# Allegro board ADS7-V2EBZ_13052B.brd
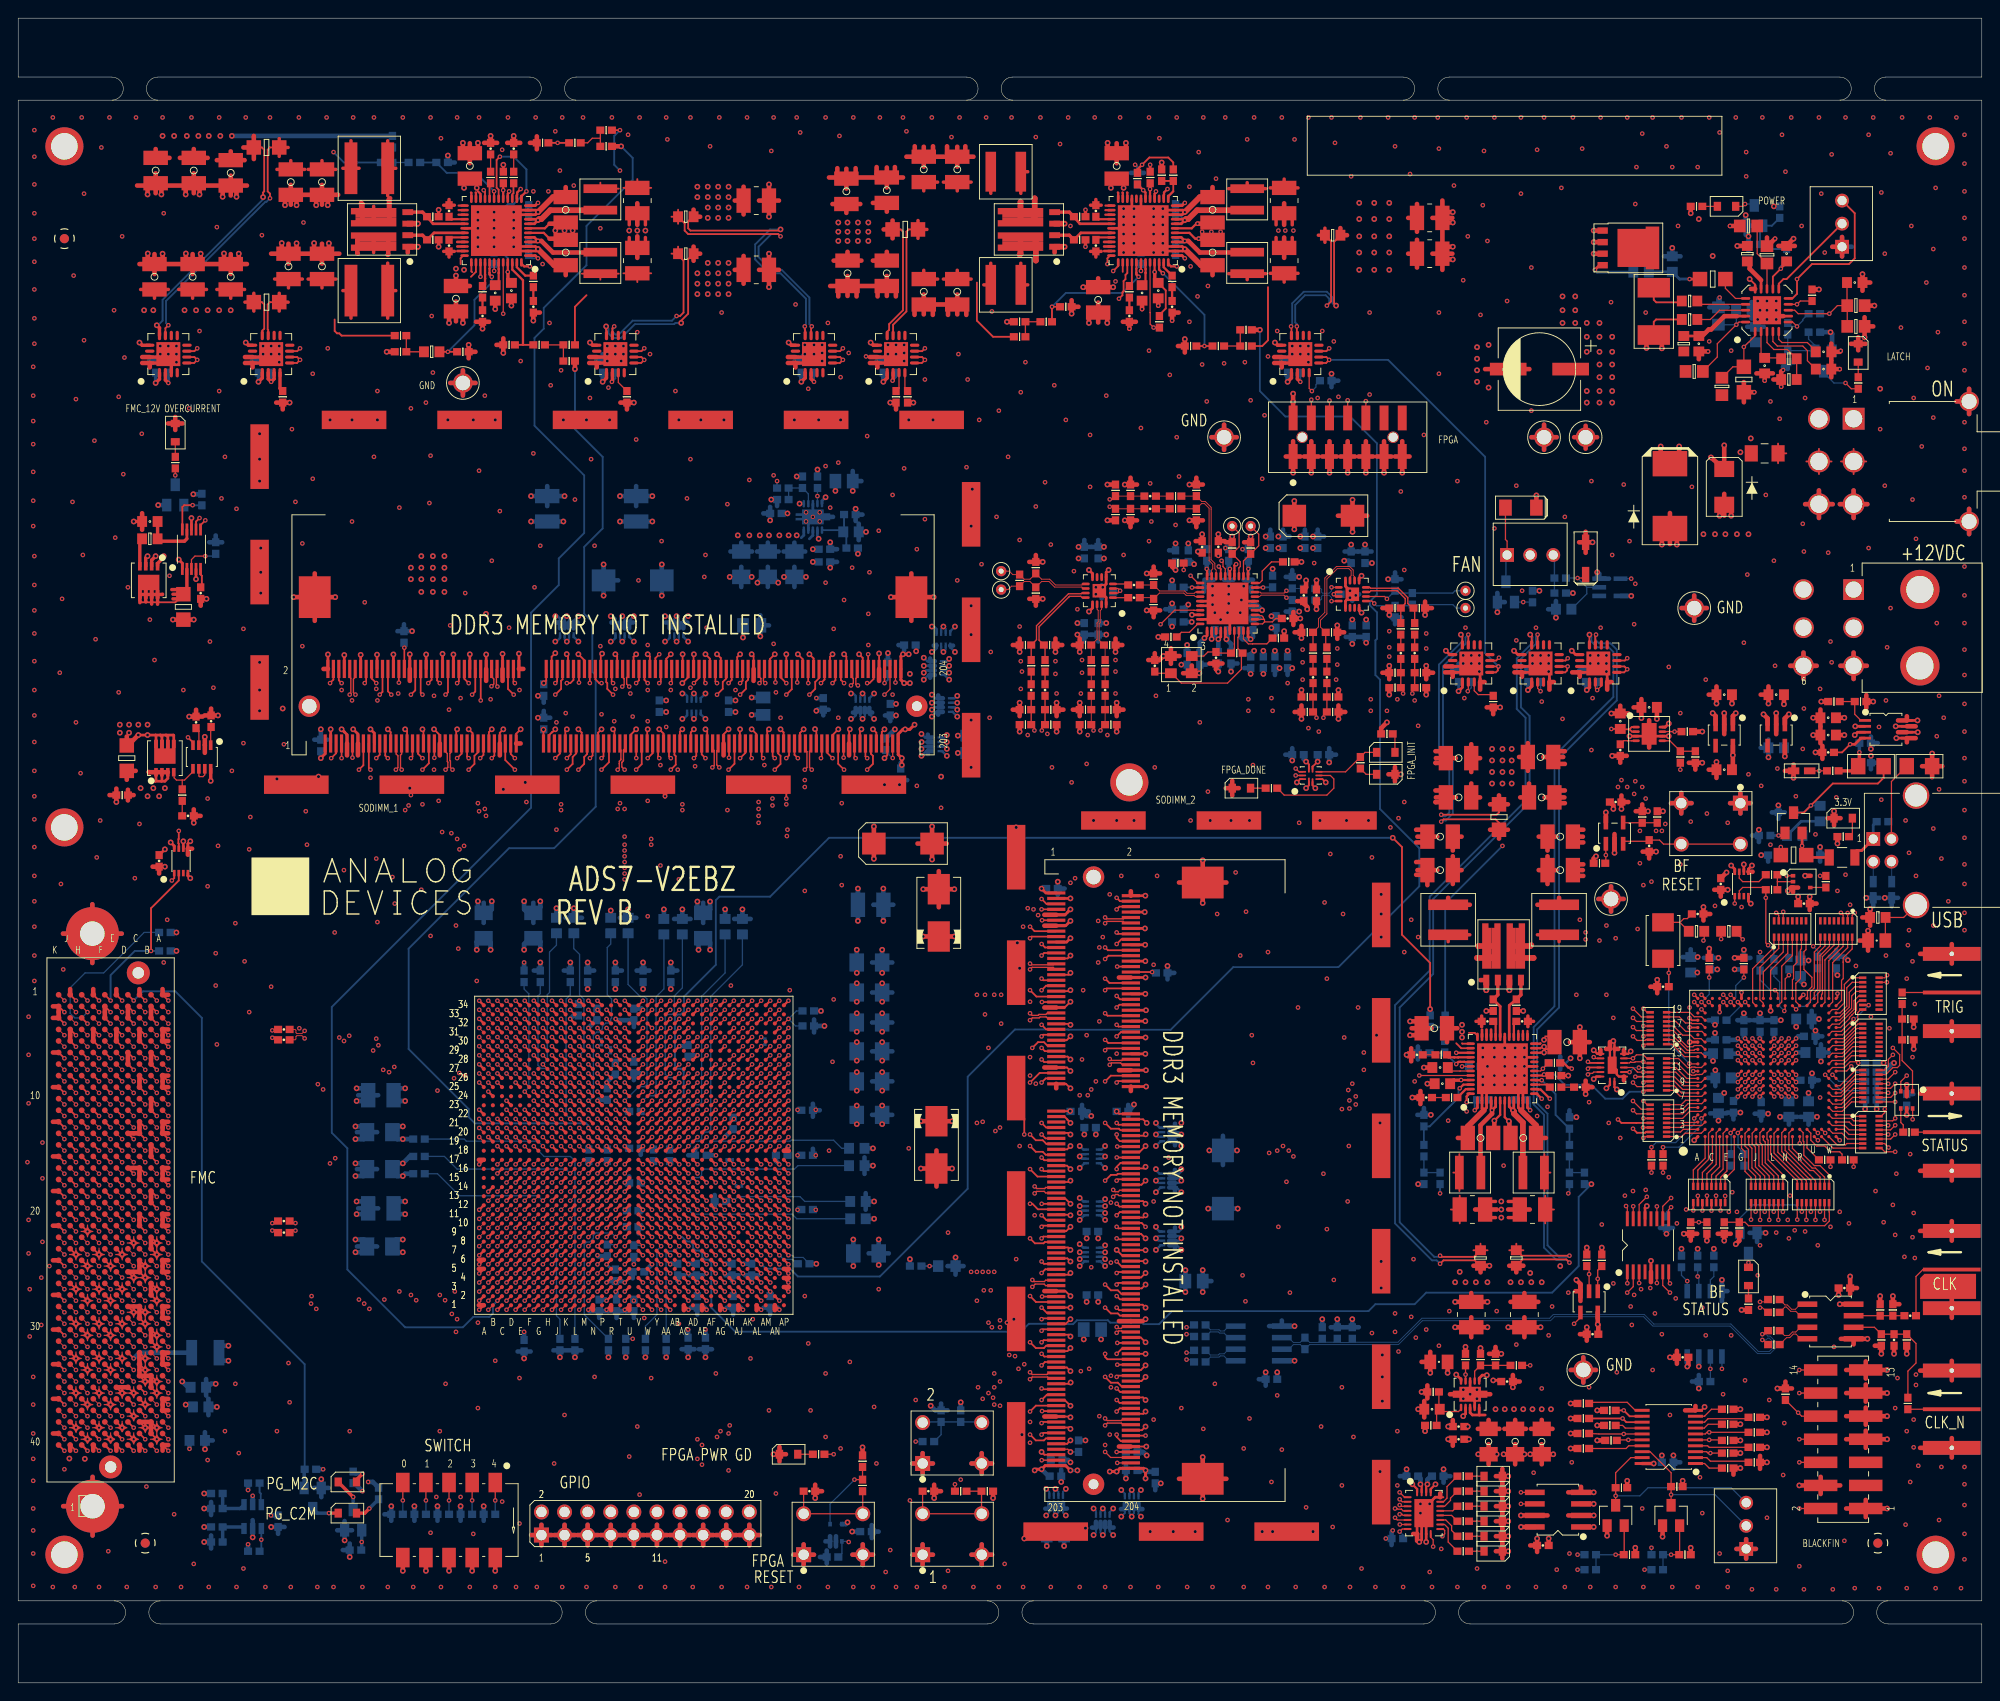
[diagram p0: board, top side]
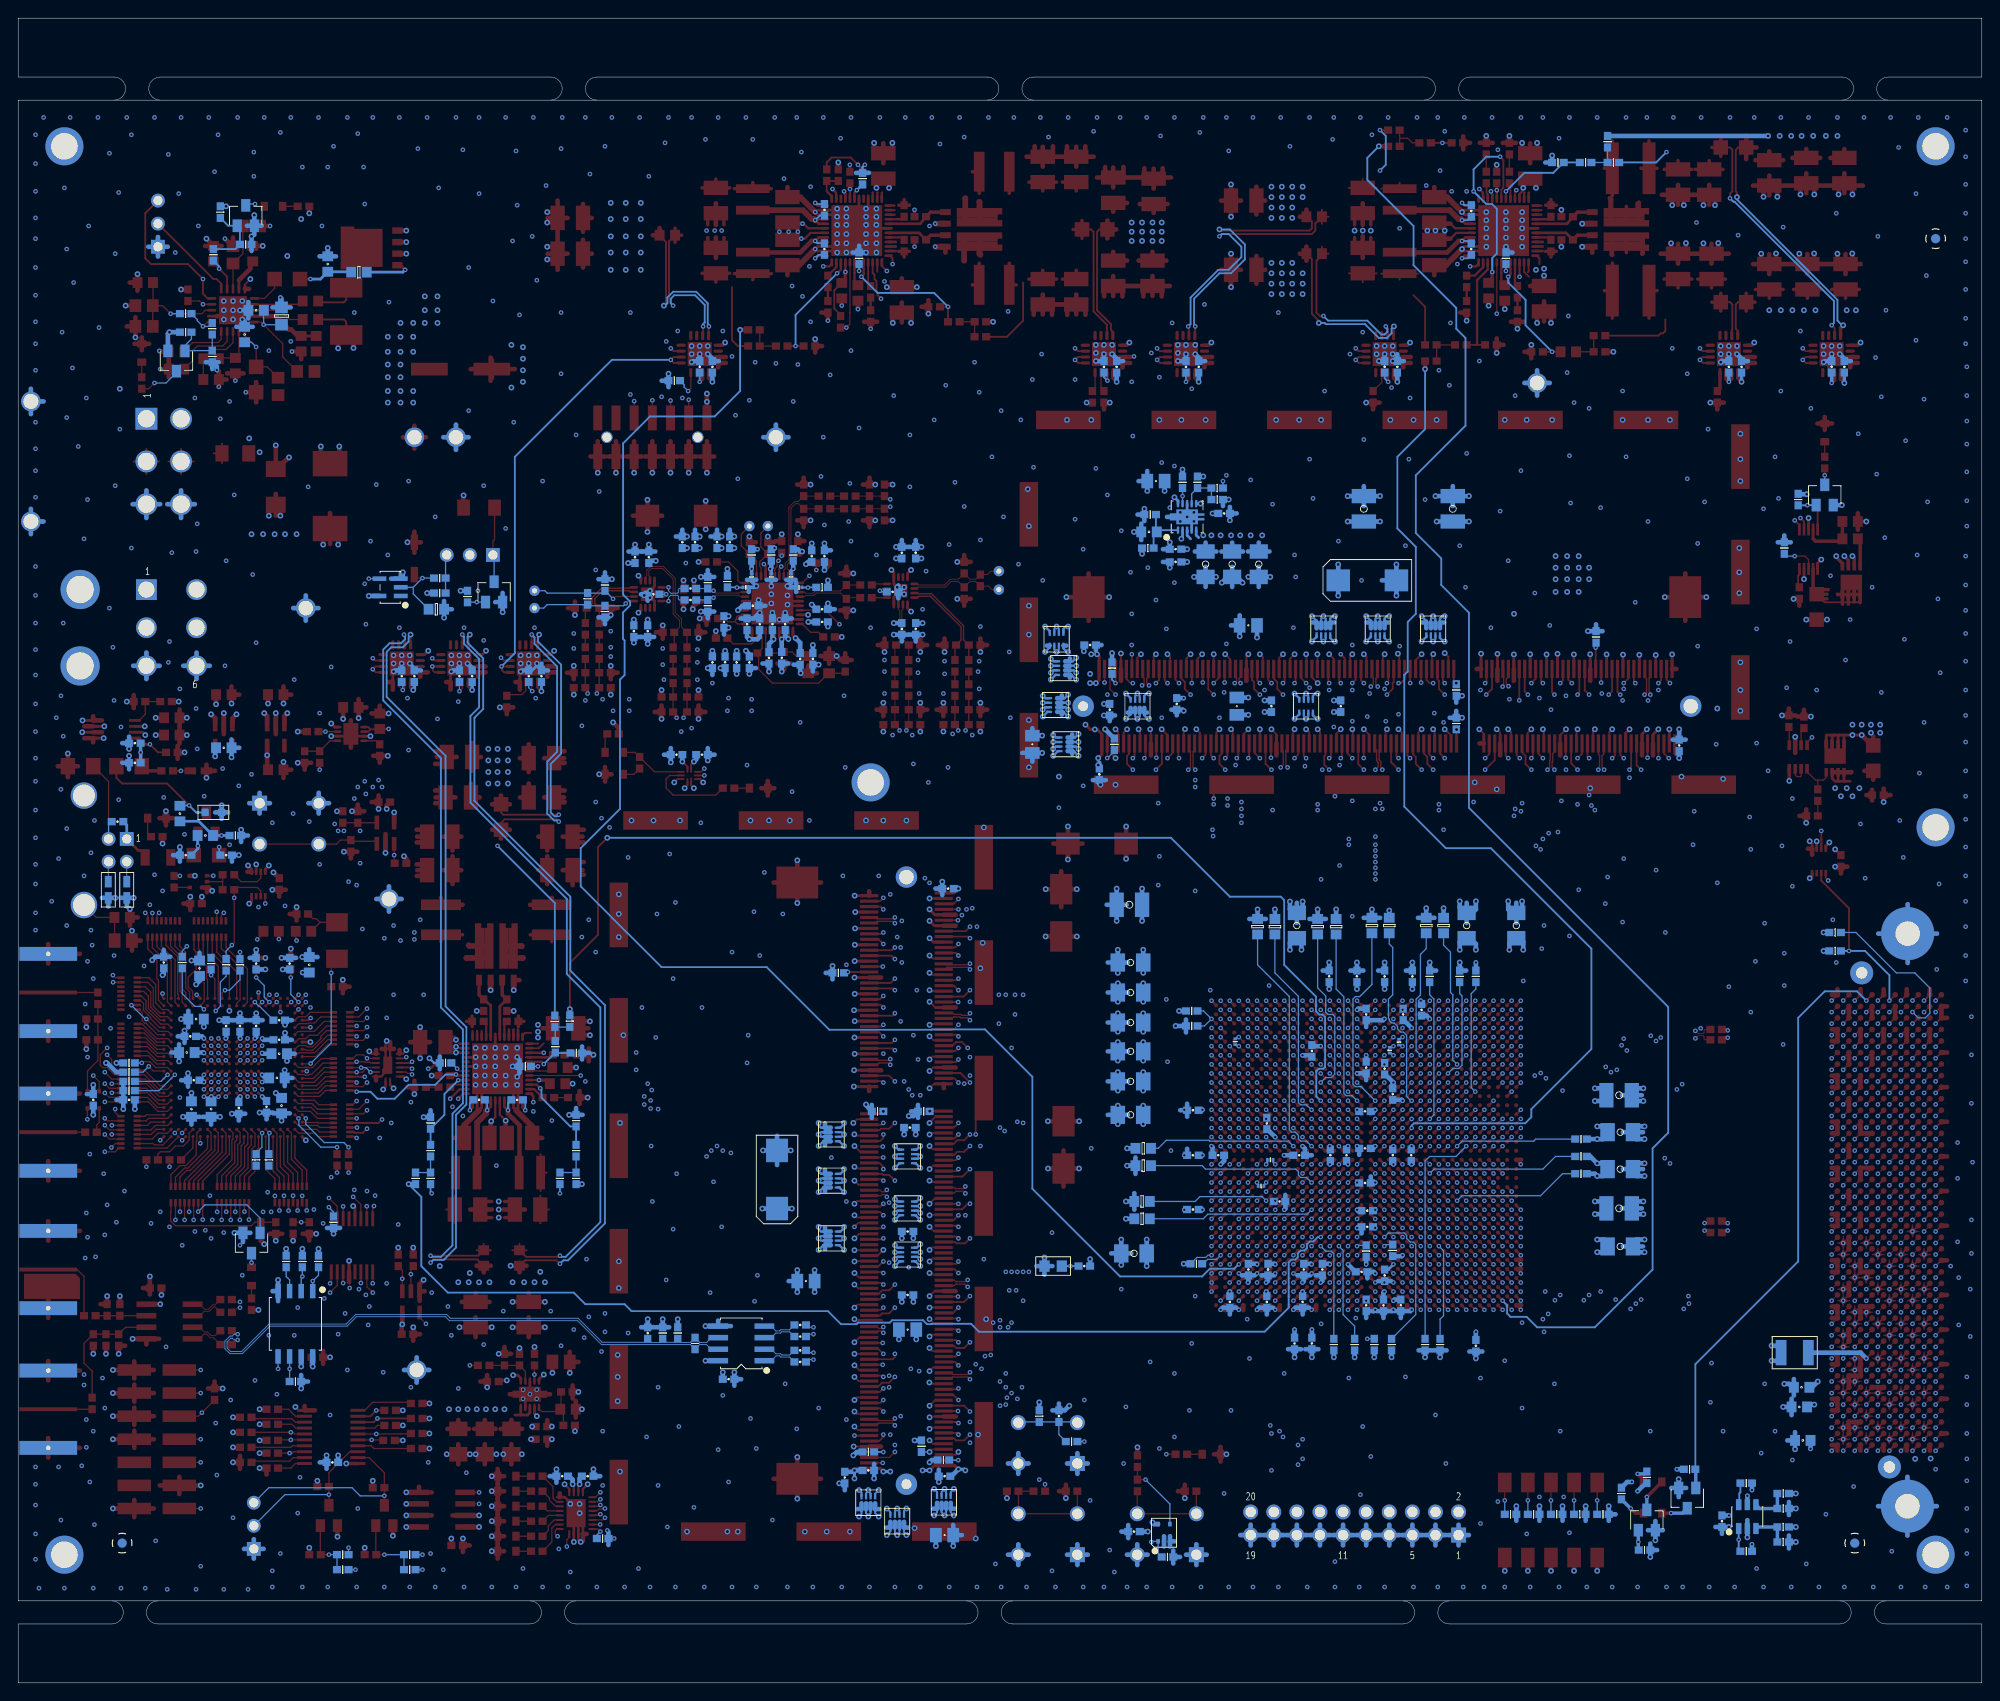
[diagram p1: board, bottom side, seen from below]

Outline 215.9 x 183.13 mm; copper layers: TOP, L2_GROUND, L3_SIGNAL, L4_GROUND, L5_SIGNAL, L6_GROUND, L7_SIGNAL, L8_GROUND, L9_SIGNAL, L10_GROUND, L11_POWER, L12_POWER, L13_POWER, L14_POWER, L15_GROUND, L16_SIGNAL, L17_GROUND, L18_SIGNAL, L19_GROUND, L20_SIGNAL, L21_GROUND, L22_SIGNAL, L23_GROUND, BOTTOM. Coordinates in mm from the lower left corner of the outline.
Outline path: 10.54,6.48 0,6.48 0,0 215.9,0 215.9,6.48 205.61,6.48 arc(204.34,7.75) 205.61,9.02 ; 10.29,174.12 arc(11.56,175.39) 10.29,176.66 0,176.66 0,183.13 215.9,183.13 215.9,176.66 205.36,176.66 ; 10.54,9.01 arc(11.81,7.75) 10.54,6.48 ; 15.37,174.12 arc(14.1,175.39) 15.37,176.66 56.26,176.66 ; 15.62,6.48 arc(14.36,7.75) 15.62,9.02 ; 15.62,6.48 58.55,6.48 ; 56.26,176.66 arc(57.53,175.38) 56.26,174.12 ; 58.54,9.01 arc(59.81,7.75) 58.54,6.48 ; 61.34,174.12 arc(60.08,175.39) 61.35,176.66 ; 63.62,6.48 arc(62.36,7.75) 63.63,9.02 ; 63.63,6.48 106.55,6.48 ; 104.27,176.66 61.34,176.66 ; 104.27,176.66 arc(105.53,175.38) 104.26,174.12 ; 106.55,9.01 arc(107.82,7.75) 106.55,6.48 ; 109.35,174.12 arc(108.08,175.39) 109.35,176.66 ; 111.63,6.48 arc(110.37,7.75) 111.64,9.02 ; 111.63,6.48 154.56,6.48 ; 152.27,176.66 109.35,176.66 ; 152.28,176.66 arc(153.54,175.38) 152.27,174.12 ; 154.56,9.01 arc(155.82,7.75) 154.55,6.48 ; 157.36,174.12 arc(156.09,175.39) 157.36,176.66 ; 159.64,6.48 arc(158.37,7.75) 159.64,9.02 ; 159.64,6.48 200.53,6.48 arc(201.8,7.75) 200.53,9.02 ; 200.28,176.66 157.35,176.66 ; 200.28,176.66 arc(201.54,175.38) 200.28,174.12 ; 205.36,174.12 arc(204.09,175.39) 205.36,176.66 ; 0,174.12 0,9.02 215.9,9.02 215.9,174.12 0,174.12

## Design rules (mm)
net group AD9577_OUT0_N: nets AD9577_OUT0_N UNNAMED_19_AD9577_I478_OUT0N
net group AD9577_OUT0_P: nets AD9577_OUT0_P UNNAMED_19_AD9577_I478_OUT0P
net group AD9577_OUT2_N: nets AD9577_OUT2_N UNNAMED_19_AD9577_I478_OUT2N
net group AD9577_OUT2_P: nets AD9577_OUT2_P UNNAMED_19_AD9577_I478_OUT2P
net group ADM1276_PWRGD: nets ADM1276_PWRGD UNNAMED_22_RES_I217_N2
net group ADP5054_#1_BST3: nets ADP5054_#1_BST3 UNNAMED_15_ADP5054_I113_SW31
net group ADP5054_#1_BST4: nets ADP5054_#1_BST4 UNNAMED_15_CAP_I42_N2
net group ADP5054_#2_BST3: nets ADP5054_#2_BST3 UNNAMED_20_ADP5054_I24_SW31
net group ADP5054_#2_BST4: nets ADP5054_#2_BST4 UNNAMED_20_ADP5054_I24_SW41
net group ADP5054_#3_BST3: nets ADP5054_#3_BST3 UNNAMED_21_ADP5054_I24_SW31
net group ADP5054_#3_BST4: nets ADP5054_#3_BST4 UNNAMED_21_ADP5054_I24_SW41
net group ARDY: nets ARDY UNNAMED_14_ADSPBF52XV3_I94_ARDY
net group AREB: nets AREB UNNAMED_14_ADSPBF52XV3_I94_AREN
net group BF_CLKBUF: nets BF_CLKBUF UNNAMED_10_ADSPBF52XV3_I35_USBX
net group BF_JTAG_EMU: nets BF_JTAG_EMU UNNAMED_10_ADSPBF52XV3_I35_EMU
net group BF_JTAG_TDO: nets BF_JTAG_TDO UNNAMED_10_ADSPBF52XV3_I35_TDO
net group CCLK: nets CCLK UNNAMED_1_CMOSNC7SZ125_I41_Y
net group DDR3-1_REF_EN: nets DDR3-1_REF_EN UNNAMED_24_ICTPS51200_I1_EN
net group DDR3-2_REF_EN: nets DDR3-2_REF_EN UNNAMED_24_ICTPS51200_I33_EN
net group FMC-1_CLK0_M2C: nets FMC-1_CLK0_M2C_N FMC-1_CLK0_M2C_P
net group FMC-1_CLK1_M2C: nets FMC-1_CLK1_M2C_N FMC-1_CLK1_M2C_P
net group FMC-1_CLK2_BIDIR: nets FMC-1_CLK2_BIDIR_N FMC-1_CLK2_BIDIR_P
net group FMC-1_CLK3_BIDIR: nets FMC-1_CLK3_BIDIR_N FMC-1_CLK3_BIDIR_P
net group FMC-1_DP0_C2M: nets FMC-1_DP0_C2M_N FMC-1_DP0_C2M_P
net group FMC-1_DP0_M2C: nets FMC-1_DP0_M2C_N FMC-1_DP0_M2C_P
net group FMC-1_DP1_C2M: nets FMC-1_DP1_C2M_N FMC-1_DP1_C2M_P
net group FMC-1_DP1_M2C: nets FMC-1_DP1_M2C_N FMC-1_DP1_M2C_P
net group FMC-1_DP2_C2M: nets FMC-1_DP2_C2M_N FMC-1_DP2_C2M_P
net group FMC-1_DP2_M2C: nets FMC-1_DP2_M2C_N FMC-1_DP2_M2C_P
net group FMC-1_DP3_C2M: nets FMC-1_DP3_C2M_N FMC-1_DP3_C2M_P
net group FMC-1_DP3_M2C: nets FMC-1_DP3_M2C_N FMC-1_DP3_M2C_P
net group FMC-1_DP4_C2M: nets FMC-1_DP4_C2M_N FMC-1_DP4_C2M_P
net group FMC-1_DP4_M2C: nets FMC-1_DP4_M2C_N FMC-1_DP4_M2C_P
net group FMC-1_DP5_C2M: nets FMC-1_DP5_C2M_N FMC-1_DP5_C2M_P
net group FMC-1_DP5_M2C: nets FMC-1_DP5_M2C_N FMC-1_DP5_M2C_P
net group FMC-1_DP6_C2M: nets FMC-1_DP6_C2M_N FMC-1_DP6_C2M_P
net group FMC-1_DP6_M2C: nets FMC-1_DP6_M2C_N FMC-1_DP6_M2C_P
net group FMC-1_DP7_C2M: nets FMC-1_DP7_C2M_N FMC-1_DP7_C2M_P
net group FMC-1_DP7_M2C: nets FMC-1_DP7_M2C_N FMC-1_DP7_M2C_P
net group FMC-1_DP8_C2M: nets FMC-1_DP8_C2M_N FMC-1_DP8_C2M_P
net group FMC-1_DP8_M2C: nets FMC-1_DP8_M2C_N FMC-1_DP8_M2C_P
net group FMC-1_DP9_C2M: nets FMC-1_DP9_C2M_N FMC-1_DP9_C2M_P
net group FMC-1_DP9_M2C: nets FMC-1_DP9_M2C_N FMC-1_DP9_M2C_P
net group FMC-1_GBTCLK0_M2C_C_N: nets FMC-1_GBTCLK0_M2C_C_N FMC-1_GBTCLK0_M2C_N
net group FMC-1_GBTCLK0_M2C_C_P: nets FMC-1_GBTCLK0_M2C_C_P FMC-1_GBTCLK0_M2C_P
net group FMC-1_GBTCLK1_M2C_C_N: nets FMC-1_GBTCLK1_M2C_C_N FMC-1_GBTCLK1_M2C_N
net group FMC-1_GBTCLK1_M2C_C_P: nets FMC-1_GBTCLK1_M2C_C_P FMC-1_GBTCLK1_M2C_P
net group FMC-1_VIO_B_M2C: nets UNNAMED_16_ADCMP671_I40_INH UNNAMED_16_ADCMP671_I40_INL
net group FPGA_GPIO_PB1: nets FPGA_GPIO_PB1 UNNAMED_25_CAP_I36_N2
net group FPGA_GPIO_PB2: nets FPGA_GPIO_PB2 UNNAMED_25_CAP_I49_N2
net group FPGA_LED0_3P3: nets FPGA_LED0_3P3 UNNAMED_25_DIOLED_I458_P
net group FPGA_LED1_3P3: nets FPGA_LED1_3P3 UNNAMED_25_DIOLED_I459_P
net group FPGA_LED2_3P3: nets FPGA_LED2_3P3 UNNAMED_25_DIOLED_I460_P
net group FPGA_LED3_3P3: nets FPGA_LED3_3P3 UNNAMED_25_DIOLED_I461_P
net group FPGA_LED4_3P3: nets FPGA_LED4_3P3 UNNAMED_25_DIOLED_I462_P
net group FPGA_LED5_3P3: nets FPGA_LED5_3P3 UNNAMED_25_DIOLED_I463_P
net group FPGA_RESETB: nets FPGA_RESETB UNNAMED_1_CAP_I46_N2
net group MGT_ALT_CLK_N: nets MGT_ALT_CLK_N UNNAMED_25_ICICS85411_I427_NQ1
net group MGT_ALT_CLK_P: nets MGT_ALT_CLK_P UNNAMED_25_ICICS85411_I427_Q1
net group MGTREFCLK1_117_C_N: nets MGTREFCLK1_117_C_N MGTREFCLK1_117_N
net group MGTREFCLK1_117_C_P: nets MGTREFCLK1_117_C_P MGTREFCLK1_117_P
net group MGTREFCLK1_118_C_N: nets MGTREFCLK1_118_C_N MGTREFCLK1_118_N
net group MGTREFCLK1_118_C_P: nets MGTREFCLK1_118_C_P MGTREFCLK1_118_P
net group SMA_GPIO0_N: nets SMA_GPIO0_N UNNAMED_25_ICICS85411_I427_NQ0
net group SMA_GPIO0_P: nets SMA_GPIO0_P UNNAMED_25_ICICS85411_I427_Q0
net group UNNAMED_1_DIOLED_I22_P: nets UNNAMED_1_DIOLED_I22_P UNNAMED_1_RES_I23_N2
net group UNNAMED_1_DIOLED_I25_P: nets UNNAMED_1_DIOLED_I25_P UNNAMED_1_DIOLED_I29_N
net group UNNAMED_10_CAP_I105_N1: nets UNNAMED_10_CAP_I105_N1 UNNAMED_10_CAP_I111_N1
net group UNNAMED_10_CAP_I121_N1: nets UNNAMED_10_CAP_I121_N1 UNNAMED_10_CAP_I121_N2
net group UNNAMED_14_ADSPBF52XV3_I94_XTAL: nets UNNAMED_14_ADSPBF52XV3_I94_XTAL UNNAMED_14_CAP_I115_N1
net group UNNAMED_16_ADM1170_I73_GATE: nets UNNAMED_16_ADM1170_I73_GATE UNNAMED_16_CAP_I78_N1
net group UNNAMED_19_ADCLK944_I308_Q2: nets UNNAMED_19_ADCLK944_I308_Q2 UNNAMED_19_ADCLK944_I308_Q2N
net group UNNAMED_19_ADCLK944_I355_Q2: nets UNNAMED_19_ADCLK944_I355_Q2 UNNAMED_19_ADCLK944_I355_Q2N
net group UNNAMED_22_ADM1178_I115_GATE: nets UNNAMED_22_ADM1178_I115_GATE UNNAMED_22_RES_I56_N2
net group UNNAMED_22_ADM1276_I200_ISET: nets UNNAMED_22_ADM1276_I200_ISET UNNAMED_22_ADM1276_I200_VCAP
net group UNNAMED_22_DIOLED_I315_P: nets UNNAMED_22_DIOLED_I315_P UNNAMED_22_RES_I263_N2
net group UNNAMED_22_DIOLED_I318_P: nets UNNAMED_22_DIOLED_I318_P UNNAMED_22_RES_I265_N2
net group UNNAMED_25_74LVC1G17_I357_A: nets UNNAMED_25_74LVC1G17_I357_A UNNAMED_25_CN3P_I305_N3
net group UNNAMED_25_CAP_I423_N2: nets UNNAMED_25_CAP_I423_N2 UNNAMED_25_CNBNC5P_I378_CNTR
net group UNNAMED_25_CNBNC5P_I329_CNTR: nets UNNAMED_25_CNBNC5P_I329_CNTR UNNAMED_25_NC7WZ04P6X_I339_Y2
net group UNNAMED_25_CNBNC5P_I336_CNTR: nets UNNAMED_25_CNBNC5P_I336_CNTR UNNAMED_25_NC7WZ04P6X_I339_A1
net group UNNAMED_25_CNBNC5P_I370_CNTR: nets UNNAMED_25_CNBNC5P_I370_CNTR UNNAMED_25_RES_I367_N2
net group UNNAMED_25_DIOLED_I452_P: nets UNNAMED_25_DIOLED_I452_P UNNAMED_25_ICFXL4245_I446_B7
net group USB_D: nets USB_D_N USB_D_P
net group XTAL1_25MHZ_AD9577: nets XTAL1_25MHZ_AD9577 XTAL2_25MHZ_AD9577
net group AD9577_OUT1_N: nets AD9577_OUT1_N SYS_CLK_N UNNAMED_19_CAP_I321_N1
net group AD9577_OUT1_P: nets AD9577_OUT1_P SYS_CLK_P UNNAMED_19_CAP_I319_N1
net group ADCMP671-1_OVB: nets ADCMP671-1_OVB ADCMP671-1_PWRGD_3P3 FMC-1_PG_C2M_3P3 FMC-1_PG_M2C_3P3 UNNAMED_16_DIOLED_I37_P UNNAMED_16_DIOLED_I63_P
net group ADM1276_LATCHB: nets ADM1276_LATCHB UNNAMED_22_ADM1276_I200_ENABLE UNNAMED_22_ADM1276_I200_OV UNNAMED_22_ADM1276_I200_SENSE UNNAMED_22_ADM1276_I200_SENSE_1 UNNAMED_22_ADM1276_I200_UV UNNAMED_22_ADM1276_I200_VCC UNNAMED_22_RES_I227_N1
net group ADP5054_#1_BST1: nets ADP5054_#1_BST1
net group ADP5054_#1_BST2: nets ADP5054_#1_BST2
net group ADP5054_#2_BST1: nets ADP5054_#2_BST1
net group ADP5054_#2_BST2: nets ADP5054_#2_BST2
net group ADP5054_#3_BST1: nets ADP5054_#3_BST1
net group ADP5054_#3_BST2: nets ADP5054_#3_BST2
net group AWEB: nets AWEB UNNAMED_1_CMOSNC7SZ125_I41_A UNNAMED_1_ICNC7WZ08K_I31_Y1 UNNAMED_14_ADSPBF52XV3_I94_AWEN
net group BF_SCL: nets BF_SCL FPGA_SCL PCA9545_SCL_MAIN_1P8 UNNAMED_12_ADSPBF52XV3_I42_SCL
net group BF_SDA: nets BF_SDA FPGA_SDA PCA9545_SDA_MAIN_1P8 UNNAMED_12_ADSPBF52XV3_I42_SDA
net group CK2DQS_MATCH: nets DDR3-1_CK0_P DDR3-1_DQS0_P DDR3-1_DQS1_P DDR3-1_DQS2_P DDR3-1_DQS3_P DDR3-1_DQS4_P DDR3-1_DQS5_P DDR3-1_DQS6_P DDR3-1_DQS7_P DDR3-2_DQS0_P DDR3-2_DQS1_P DDR3-2_DQS2_P DDR3-2_DQS3_P DDR3-2_DQS4_P DDR3-2_DQS5_P DDR3-2_DQS6_P DDR3-2_DQS7_P
net group DDR3-1_CK0: nets DDR3-1_CK0_N
net group DDR3-1_CK1: nets DDR3-1_CK1_N
net group DDR3-1_CLK_REF_N: nets DDR3-1_CLK_REF_N UNNAMED_19_ADCLK944_I308_Q0N UNNAMED_19_CAP_I334_N1
net group DDR3-1_CLK_REF_P: nets DDR3-1_CLK_REF_P UNNAMED_19_ADCLK944_I308_Q0 UNNAMED_19_CAP_I331_N1
net group DDR3-1_DQS0: nets DDR3-1_DQS0_N
net group DDR3-1_DQS1: nets DDR3-1_DQS1_N
net group DDR3-1_DQS2: nets DDR3-1_DQS2_N
net group DDR3-1_DQS3: nets DDR3-1_DQS3_N
net group DDR3-1_DQS4: nets DDR3-1_DQS4_N
net group DDR3-1_DQS5: nets DDR3-1_DQS5_N
net group DDR3-1_DQS6: nets DDR3-1_DQS6_N
net group DDR3-1_DQS7: nets DDR3-1_DQS7_N
net group DDR3-1_MISC_BUS: nets DDR3-1_RASB DDR3-1_RESETB DDR3-1_S0B DDR3-1_WEB
net group DDR3-1_SYS_CLK_N: nets DDR3-1_SYS_CLK_N UNNAMED_19_ADCLK944_I355_Q0N UNNAMED_19_CAP_I366_N1
net group DDR3-1_SYS_CLK_P: nets DDR3-1_SYS_CLK_P UNNAMED_19_ADCLK944_I355_Q0 UNNAMED_19_CAP_I362_N1
net group DDR3-2_CK0: nets DDR3-2_CK0_N
net group DDR3-2_CK1: nets DDR3-2_CK1_N
net group DDR3-2_CLK_REF_N: nets DDR3-2_CLK_REF_N UNNAMED_19_ADCLK944_I308_Q1N UNNAMED_19_CAP_I347_N1
net group DDR3-2_CLK_REF_P: nets DDR3-2_CLK_REF_P UNNAMED_19_ADCLK944_I308_Q1 UNNAMED_19_CAP_I342_N1
net group DDR3-2_DQS0: nets DDR3-2_DQS0_N
net group DDR3-2_DQS1: nets DDR3-2_DQS1_N
net group DDR3-2_DQS2: nets DDR3-2_DQS2_N
net group DDR3-2_DQS3: nets DDR3-2_DQS3_N
net group DDR3-2_DQS4: nets DDR3-2_DQS4_N
net group DDR3-2_DQS5: nets DDR3-2_DQS5_N
net group DDR3-2_DQS6: nets DDR3-2_DQS6_N
net group DDR3-2_MISC_BUS: nets DDR3-2_RASB DDR3-2_RESETB DDR3-2_S0B DDR3-2_WEB
net group DDR3-2_SYS_CLK_N: nets DDR3-2_SYS_CLK_N UNNAMED_19_ADCLK944_I355_Q1N UNNAMED_19_CAP_I380_N1
net group DDR3-2_SYS_CLK_P: nets DDR3-2_SYS_CLK_P UNNAMED_19_ADCLK944_I355_Q1 UNNAMED_19_CAP_I375_N1
net group FMC-1_HA00_CC: nets FMC-1_HA00_N_CC
net group FMC-1_HA01_CC: nets FMC-1_HA01_N_CC
net group FMC-1_HA02: nets FMC-1_HA02_N
net group FMC-1_HA03: nets FMC-1_HA03_N
net group FMC-1_HA04: nets FMC-1_HA04_N
net group FMC-1_HA05: nets FMC-1_HA05_N
net group FMC-1_HA06: nets FMC-1_HA06_N
net group FMC-1_HA07: nets FMC-1_HA07_N
net group FMC-1_HA08: nets FMC-1_HA08_N
net group FMC-1_HA09: nets FMC-1_HA09_N
net group FMC-1_HA10: nets FMC-1_HA10_N
net group FMC-1_HA11: nets FMC-1_HA11_N
net group FMC-1_HA12: nets FMC-1_HA12_N
net group FMC-1_HA13: nets FMC-1_HA13_N
net group FMC-1_HA14: nets FMC-1_HA14_N
net group FMC-1_HA15: nets FMC-1_HA15_N
net group FMC-1_HA16: nets FMC-1_HA16_N
net group FMC-1_HA17_CC: nets FMC-1_HA17_N_CC
net group FMC-1_HA18: nets FMC-1_HA18_N
net group FMC-1_HA19: nets FMC-1_HA19_N
net group FMC-1_HA20: nets FMC-1_HA20_N
net group FMC-1_HA21: nets FMC-1_HA21_N
net group FMC-1_HA22: nets FMC-1_HA22_N
net group FMC-1_HA23: nets FMC-1_HA23_N
net group FMC-1_HB00_CC: nets FMC-1_HB00_N_CC
net group FMC-1_HB01: nets FMC-1_HB01_N
net group FMC-1_HB02: nets FMC-1_HB02_N
net group FMC-1_HB03: nets FMC-1_HB03_N
net group FMC-1_HB04: nets FMC-1_HB04_N
net group FMC-1_HB05: nets FMC-1_HB05_N
net group FMC-1_HB06_CC: nets FMC-1_HB06_N_CC
net group FMC-1_HB07: nets FMC-1_HB07_N
net group FMC-1_HB08: nets FMC-1_HB08_N
net group FMC-1_HB09: nets FMC-1_HB09_N
net group FMC-1_HB10: nets FMC-1_HB10_N
net group FMC-1_HB11: nets FMC-1_HB11_N
net group FMC-1_HB12: nets FMC-1_HB12_N
net group FMC-1_HB13: nets FMC-1_HB13_N
net group FMC-1_HB14: nets FMC-1_HB14_N
net group FMC-1_HB15: nets FMC-1_HB15_N
net group FMC-1_HB16: nets FMC-1_HB16_N
net group FMC-1_HB17_CC: nets FMC-1_HB17_N_CC
net group FMC-1_HB18: nets FMC-1_HB18_N
net group FMC-1_HB19: nets FMC-1_HB19_N
net group FMC-1_HB20: nets FMC-1_HB20_N
net group FMC-1_HB21: nets FMC-1_HB21_N
net group FMC-1_LA00_CC: nets FMC-1_LA00_N_CC
net group FMC-1_LA01_CC: nets FMC-1_LA01_N_CC
net group FMC-1_LA02: nets FMC-1_LA02_N
net group FMC-1_LA03: nets FMC-1_LA03_N
net group FMC-1_LA04: nets FMC-1_LA04_N
net group FMC-1_LA05: nets FMC-1_LA05_N
net group FMC-1_LA06: nets FMC-1_LA06_N
net group FMC-1_LA07: nets FMC-1_LA07_N
net group FMC-1_LA08: nets FMC-1_LA08_N
net group FMC-1_LA09: nets FMC-1_LA09_N
net group FMC-1_LA10: nets FMC-1_LA10_N
net group FMC-1_LA11: nets FMC-1_LA11_N
net group FMC-1_LA12: nets FMC-1_LA12_N
net group FMC-1_LA13: nets FMC-1_LA13_N
net group FMC-1_LA14: nets FMC-1_LA14_N
net group FMC-1_LA15: nets FMC-1_LA15_N
net group FMC-1_LA16: nets FMC-1_LA16_N
net group FMC-1_LA17_CC: nets FMC-1_LA17_N_CC
net group FMC-1_LA18_CC: nets FMC-1_LA18_N_CC
net group FMC-1_LA19: nets FMC-1_LA19_N
net group FMC-1_LA20: nets FMC-1_LA20_N
net group FMC-1_LA21: nets FMC-1_LA21_N
net group FMC-1_LA22: nets FMC-1_LA22_N
net group FMC-1_LA23: nets FMC-1_LA23_N
net group FMC-1_LA24: nets FMC-1_LA24_N
net group FMC-1_LA25: nets FMC-1_LA25_N
net group FMC-1_LA26: nets FMC-1_LA26_N
net group FMC-1_LA27: nets FMC-1_LA27_N
net group FMC-1_LA28: nets FMC-1_LA28_N
net group FMC-1_LA29: nets FMC-1_LA29_N
net group FMC-1_LA30: nets FMC-1_LA30_N
net group FMC-1_LA31: nets FMC-1_LA31_N
net group FMC-1_LA32: nets FMC-1_LA32_N
net group FMC-1_LA33: nets FMC-1_LA33_N
net group UNNAMED_22_ADM1276_I200_GATE: nets UNNAMED_22_ADM1276_I200_GATE UNNAMED_22_CAP_I213_N1 UNNAMED_22_RES_I212_N2

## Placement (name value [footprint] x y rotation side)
C1  10UF  [C1210]  49.66 166.88 90 top
C2  1000PF  [C0402]  51.94 168.78 270 top
C3  1000PF  [C0402]  54.48 168.78 270 top
C4  100UF  [C1210]  99.57 166.5 90 top
C5  100UF  [C1210]  103.25 166.5 90 top
C6  10UF  [C1210]  120.78 166.88 90 top
C7  100UF  [C1210]  15.11 166.37 270 top
C8  100UF  [C1210]  19.3 166.37 270 top
C9  100UF  [C1210]  23.37 166.12 270 top
C10  100UF  [C1210]  29.97 165.1 270 top
C11  100UF  [C1210]  33.4 165.1 270 top
C12  0.1UF  [C0402]  47.37 161.93 90 top
C13  10UF  [C1210]  60.2 162.05 90 top
C14  47UF  [C1210-2]  68.07 163.07 270 top
C15  47UF  [C1210-2]  81.15 163.07 0 top
C16  100UF  [C1210]  91.06 164.08 90 top
C17  100UF  [C1210]  95.5 164.21 90 top
C18  0.1UF  [C0402]  118.49 161.93 90 top
C19  10UF  [C1210]  131.32 162.05 90 top
C20  47UF  [C1210-2]  139.19 163.07 270 top
C21  0.1UF  [C0402]  47.37 158.12 270 top
C22  10UF  [C1210]  60.2 157.35 270 top
C23  47UF  [C1210-2]  68.07 156.46 90 top
C24  0.1UF  [C0402]  118.49 158.12 270 top
C25  10UF  [C1210]  131.32 157.35 270 top
C26  47UF  [C1210-2]  139.19 156.46 90 top
C27  47UF  [C1210-2]  155.19 161.16 0 top
C28  47UF  [C1210-2]  155.19 157.23 0 top
C29  0.01UF  [C0603]  194.44 157.23 270 top
C30  100UF  [C1210]  14.99 154.69 90 top
C31  100UF  [C1210]  19.18 154.69 90 top
C32  100UF  [C1210]  23.37 154.69 90 top
C33  100UF  [C1210]  29.72 155.83 90 top
C34  100UF  [C1210]  33.4 155.83 90 top
C35  10UF  [C1210]  48.13 152.27 270 top
C36  1UF  [C0603]  52.45 152.91 90 top
C37  1UF  [C0603]  54.23 153.16 270 top
C38  1000PF  [C0402]  56.64 151.38 90 top
C39  47UF  [C1210-2]  81.15 155.45 0 top
C40  100UF  [C1210]  91.19 155.07 270 top
C41  100UF  [C1210]  95.5 155.07 270 top
C42  100UF  [C1210]  99.57 153.03 270 top
C43  100UF  [C1210]  103.25 153.03 270 top
C44  10UF  [C1210]  118.75 152.15 270 top
C45  1UF  [C0603]  123.57 152.91 90 top
C46  1UF  [C0603]  125.35 153.16 270 top
C47  1000PF  [C0402]  126.87 151.38 90 top
C48  0.1UF  [C0603]  201.93 154.05 180 top
C49  1000PF  [C0402]  51.05 150.37 90 top
C50  1000PF  [C0402]  122.17 150.37 90 top
C51  0.33UF  [C0603]  184.78 147.32 90 top
C52  0.1UF  [C0603]  198.5 146.43 180 top
C53  1UF  [C0603]  192.02 144.91 90 top
C54  0.01UF  [C0603]  198.5 144.53 180 top
C55  22NF  [C0603]  14.48 127.76 0 top
C56  0.1UF  [C0402]  124.46 130.56 180 top
C57  0.1UF  [C0402]  124.46 129.16 180 top
C58  330UF  [C7343H162]  143.51 128.4 0 top
C59  0.1UF  [C0402]  122.68 120.78 180 top
C60  0.1UF  [C0402]  130.17 124.97 270 top
C61  0.01UF  [C0402]  131.95 124.97 270 top
C62  0.33UF  [C0402]  20.07 119.89 90 top
C63  0.1UF  [C0402]  122.68 119.38 180 top
C64  0.22UF  [C0402]  139.57 117.09 180 top
C65  0.01UF  [C0402]  141.35 119.63 90 top
C66  0.1UF  [C0402]  142.75 119.63 90 top
C67  22PF  [C0402]  124.97 111.89 90 top
C68  22PF  [C0402]  131.7 112.78 270 top
C69  0.1UF  [C0402]  142.37 110.62 270 top
C70  0.1UF  [C0402]  143.89 110.62 270 top
C71  0.1UF  [C0402]  152.02 113.28 270 top
C72  0.1UF  [C0402]  153.54 113.28 270 top
C73  1UF  [C0402]  19.56 105.66 90 top
C74  0.33UF  [C0402]  21.21 105.79 90 top
C75  0.1UF  [C0402]  111.38 109.22 270 top
C76  0.1UF  [C0402]  112.9 109.22 270 top
C77  0.1UF  [C0402]  117.98 109.22 270 top
C78  0.1UF  [C0402]  119.51 109.22 270 top
C79  1UF  [C0603]  176.15 105.79 270 top
C80  1UF  [C0603]  179.32 107.31 0 top
C81  1UF  [C0603]  187.58 108.71 0 top
C82  1UF  [C0603]  193.29 108.71 0 top
C83  2.2UF  [C0603]  199.01 106.17 0 top
C84  100UF  [C1210]  158.37 101.73 180 top
C85  100UF  [C1210]  167.39 101.85 0 top
C86  0.01UF  [C0402]  176.15 102.62 270 top
C87  1UF  [C0603]  187.58 100.46 0 top
C88  2.2UF  [C0603]  199.01 104.27 0 top
C89  0.01UF  [C0402]  199.01 102.36 0 top
C90  4700PF  [C0402]  18.67 95.38 0 top
C91  100UF  [C1210]  156.34 93.09 180 top
C92  100UF  [C1210]  158.37 97.41 180 top
C93  100UF  [C1210]  167.51 97.41 0 top
C94  100UF  [C1210]  169.55 93.09 0 top
C95  0.1UF  [C0402]  175.64 96.9 0 top
C96  0.1UF  [C0402]  15.49 90.42 90 top
C97  330UF  [C7343H162]  97.28 92.33 0 top
C98  100UF  [C1210]  156.34 89.41 180 top
C99  100UF  [C1210]  169.55 89.41 0 top
C100  1UF  [C0402]  179.32 92.08 90 top
C101  0.1UF  [C0402]  187.2 87.88 270 top
C102  0.1UF  [C0402]  196.34 85.73 0 top
C103  680UF  [C7343-43]  101.22 84.71 90 top
C104  8.2PF  [C0402]  184.66 84.58 0 top
C105  10000PF  [C0805]  204.34 81.66 180 top
C106  8.2PF  [C0402]  180.85 76.58 180 top
C107  0.1UF  [C0402]  29.21 71.88 0 top
C108  0.1UF  [C0402]  29.21 70.74 0 top
C109  10UF  [C1210]  155.7 72.01 180 top
C110  0.1UF  [C0402]  161.54 72.77 180 top
C111  0.1UF  [C0402]  165.35 72.77 0 top
C112  10UF  [C1210]  170.31 70.48 0 top
C113  1000PF  [C0402]  153.8 69.09 0 top
C114  1UF  [C0603]  156.34 67.69 0 top
C115  1UF  [C0603]  156.59 65.91 180 top
C116  1000PF  [C0402]  171.7 65.53 180 top
C117  1000PF  [C0402]  154.81 64.39 0 top
C118  10UF  [C1210]  160.78 59.94 180 top
C119  10UF  [C1210]  165.48 59.94 0 top
C120  680UF  [C7343-43]  100.97 59.18 270 top
C121  0.1UF  [C0402]  29.21 50.8 0 top
C122  47UF  [C1210-2]  159.89 52.07 0 top
C123  47UF  [C1210-2]  166.5 52.07 180 top
C124  0.1UF  [C0402]  29.21 49.53 0 top
C125  0.1UF  [C0402]  207.65 64.14 90 bottom
C126  0.1UF  [C0402]  200.79 43.43 0 top
C127  0.1UF  [C0402]  208.03 40.39 0 top
C128  47UF  [C1210-2]  159.77 40.51 270 top
C129  47UF  [C1210-2]  165.61 40.51 270 top
C130  0.1UF  [C0402]  206.25 37.72 90 top
C131  4.7UF  [C0805]  156.21 35.31 0 top
C132  0.1UF  [C0402]  173.1 38.35 0 top
C133  0.1UF  [C0402]  183.01 35.81 180 top
C134  1000PF  [C0603]  155.45 30.1 0 top
C135  0.1UF  [C0402]  163.7 33.15 180 top
C136  0.1UF  [C0402]  158.37 28.19 0 top
C137  0.1UF  [C0402]  158.37 26.8 0 top
C138  10UF  [C1206]  161.67 26.54 90 top
C139  10UF  [C1206]  164.59 26.54 90 top
C140  10UF  [C1206]  167.51 26.54 90 top
C141  0.1UF  [C0402]  101.47 29.34 270 bottom
C142  0.1UF  [C0402]  100.08 21.08 180 top
C143  0.1UF  [C0402]  167.64 15.11 0 top
C144  0.1UF  [C0402]  127.25 162.05 270 bottom
C145  0.1UF  [C0402]  56.13 161.93 270 bottom
C146  0.1UF  [C0402]  127.25 157.73 90 bottom
C147  0.1UF  [C0402]  56.13 157.73 90 bottom
C148  0.033UF  [C0603]  181.86 156.08 90 bottom
C149  0.01UF  [C0603]  191.01 148.34 270 bottom
C150  0.1UF  [C0603]  189.74 151 180 bottom
C151  4.7UF  [C0402]  140.97 144.78 90 bottom
C152  4.7UF  [C0402]  139.57 144.78 90 bottom
C153  4.7UF  [C0402]  96.52 144.78 90 bottom
C154  4.7UF  [C0402]  95.12 144.78 90 bottom
C155  4.7UF  [C0402]  87.5 144.78 90 bottom
C156  4.7UF  [C0402]  86.11 144.78 90 bottom
C157  4.7UF  [C0402]  65.66 144.78 90 bottom
C158  4.7UF  [C0402]  64.26 144.78 90 bottom
C159  4.7UF  [C0402]  27.81 144.78 90 bottom
C160  4.7UF  [C0402]  26.42 144.78 90 bottom
C161  4.7UF  [C0402]  16.51 144.78 90 bottom
C162  4.7UF  [C0402]  15.11 144.78 90 bottom
C163  4.7UF  [C0805]  90.81 132.21 180 bottom
C164  1000PF  [C0603]  91.57 126.62 180 bottom
C165  0.1UF  [C0402]  83.31 128.65 0 bottom
C166  100UF  [C1210]  67.95 129.16 270 bottom
C167  100UF  [C1210]  58.17 129.16 270 bottom
C168  0.01UF  [C0402]  148.08 123.82 270 bottom
C169  0.1UF  [C0402]  146.56 123.82 270 bottom
C170  0.1UF  [C0402]  142.88 125.48 270 bottom
C171  0.01UF  [C0402]  141.48 125.48 270 bottom
C172  0.1UF  [C0402]  139.06 125.48 270 bottom
C173  0.01UF  [C0402]  137.67 125.48 270 bottom
C174  0.1UF  [C0201]  135.25 121.67 270 bottom
C175  0.1UF  [C0201]  133.1 121.67 270 bottom
C176  0.1UF  [C0201]  130.94 121.67 270 bottom
C177  0.1UF  [C0402]  128.65 123.95 270 bottom
C178  0.01UF  [C0402]  127.25 123.95 270 bottom
C179  0.01UF  [C0402]  118.75 124.33 270 bottom
C180  0.1UF  [C0402]  117.22 124.33 270 bottom
C181  0.1UF  [C0402]  88.65 124.71 180 bottom
C182  0.1UF  [C0402]  88.65 123.32 180 bottom
C183  10UF  [C1206]  85.34 123.06 90 bottom
C184  10UF  [C1206]  82.42 123.06 90 bottom
C185  10UF  [C1206]  79.5 123.06 90 bottom
C186  330UF  [C7343H162]  67.56 121.28 180 bottom
C187  0.01UF  [C0402]  148.21 115.7 90 bottom
C188  0.1UF  [C0402]  146.69 115.7 90 bottom
C189  0.1UF  [C0402]  146.05 119.76 180 bottom
C190  0.1UF  [C0402]  141.99 120.4 0 bottom
C191  0.1UF  [C0402]  141.99 119.13 0 bottom
C192  0.1UF  [C0402]  138.3 116.71 90 bottom
C193  0.1UF  [C0201]  135.89 120.52 180 bottom
C194  0.1UF  [C0402]  135.76 116.46 270 bottom
C195  0.01UF  [C0402]  135.13 118.49 0 bottom
C196  0.01UF  [C0402]  134.37 116.46 270 bottom
C197  0.01UF  [C0402]  132.97 116.46 270 bottom
C198  0.1UF  [C0402]  131.57 116.46 270 bottom
C199  0.1UF  [C0201]  130.05 120.52 0 bottom
C200  0.01UF  [C0402]  127.51 118.11 0 bottom
C201  0.1UF  [C0402]  127.51 116.71 0 bottom
C202  0.1UF  [C0402]  119.76 120.02 0 bottom
C203  0.01UF  [C0402]  118.75 115.95 90 bottom
C204  0.1UF  [C0402]  117.22 115.95 90 bottom
C205  10UF  [C0805]  80.64 116.33 180 bottom
C206  4.7UF  [C0402]  173.74 110.74 90 bottom
C207  4.7UF  [C0402]  172.34 110.74 90 bottom
C208  4.7UF  [C0402]  167.39 110.74 90 bottom
C209  4.7UF  [C0402]  165.99 110.74 90 bottom
C210  4.7UF  [C0402]  159.77 110.74 90 bottom
C211  4.7UF  [C0402]  158.37 110.74 90 bottom
C212  0.1UF  [C0402]  139.57 112.27 90 bottom
C213  0.01UF  [C0402]  138.18 112.27 90 bottom
C214  0.1UF  [C0402]  136.91 112.27 90 bottom
C215  0.01UF  [C0402]  135.51 112.27 90 bottom
C216  0.1UF  [C0402]  133.35 112.78 90 bottom
C217  0.01UF  [C0402]  131.95 112.78 90 bottom
C218  0.1UF  [C0402]  129.92 112.65 90 bottom
C219  0.01UF  [C0402]  128.52 112.65 90 bottom
C220  0.1UF  [C0402]  98.04 114.17 180 bottom
C221  0.1UF  [C0402]  95.89 107.06 270 bottom
C222  0.1UF  [C0402]  88.52 107.7 270 bottom
C223  10UF  [C0805]  81.92 107.44 90 bottom
C224  0.1UF  [C0402]  78.11 107.44 270 bottom
C225  0.1UF  [C0402]  70.48 107.44 270 bottom
C226  0.1UF  [C0402]  203.07 103.38 0 bottom
C227  4.7UF  [C0402]  203.07 101.22 0 bottom
C228  1UF  [C0603]  193.29 102.87 0 bottom
C229  0.1UF  [C0402]  143.51 102.11 180 bottom
C230  0.1UF  [C0402]  140.72 102.11 0 bottom
C231  10UF  [C0805]  104.39 103.25 90 bottom
C232  0.01UF  [C0402]  33.27 103.12 270 bottom
C233  0.033UF  [C0603]  198.12 95.63 90 bottom
C234  0.1UF  [C0402]  97.03 99.95 90 bottom
C235  0.1UF  [C0402]  204.98 94.74 0 bottom
C236  1UF  [C0402]  197.49 91.06 0 bottom
C237  0.33UF  [C0603]  195.33 93.22 180 bottom
C238  1UF  [C0402]  193.04 91.06 180 bottom
C239  0.01UF  [C0402]  113.67 87.38 180 bottom
C240  47UF  [C1210]  93.73 85.6 180 bottom
C241  100UF  [C1206H71]  75.31 83.31 270 bottom
C242  100UF  [C1206H71]  56.64 83.31 270 bottom
C243  100UF  [C1206H71]  51.18 83.31 270 bottom
C244  0.1UF  [C0402]  199.9 79.25 90 bottom
C245  1UF  [C0603]  195.96 78.61 90 bottom
C246  0.1UF  [C0402]  189.74 79.12 90 bottom
C247  0.1UF  [C0402]  186.06 79.12 90 bottom
C248  1UF  [C0603]  183.9 78.99 90 bottom
C249  100UF  [C1206H71]  93.6 79.25 180 bottom
C250  100UF  [C1206H71]  93.6 75.95 180 bottom
C251  0.1UF  [C0402]  71.75 77.72 270 bottom
C252  0.1UF  [C0402]  68.71 77.72 270 bottom
C253  0.1UF  [C0402]  65.66 77.72 270 bottom
C254  0.1UF  [C0402]  62.61 77.72 270 bottom
C255  0.1UF  [C0402]  196.98 71.12 0 bottom
C256  1UF  [C0603]  196.34 73.03 0 bottom
C257  0.1UF  [C0402]  193.04 72.26 90 bottom
C258  0.1UF  [C0402]  191.52 72.26 90 bottom
C259  0.1UF  [C0402]  189.74 72.26 90 bottom
C260  0.1UF  [C0402]  187.2 72.9 180 bottom
C261  0.1UF  [C0402]  187.2 70.74 180 bottom
C262  100UF  [C1206H71]  93.6 72.64 180 bottom
C263  0.1UF  [C0402]  67.69 73.53 90 bottom
C264  0.1UF  [C0402]  63.63 73.53 90 bottom
C265  0.1UF  [C0402]  61.59 74.04 270 bottom
C266  1UF  [C0603]  197.36 69.34 0 bottom
C267  0.1UF  [C0402]  196.6 66.29 0 bottom
C268  1UF  [C0603]  187.45 66.55 180 bottom
C269  1UF  [C0603]  187.2 69.22 180 bottom
C270  100UF  [C1206H71]  93.6 69.47 180 bottom
C271  47UF  [C1206]  93.6 66.17 180 bottom
C272  0.1UF  [C0402]  73.66 69.52 90 bottom
C273  0.1UF  [C0402]  67.69 67.69 90 bottom
C274  0.1UF  [C0402]  65.66 67.56 90 bottom
C275  0.1UF  [C0402]  203.71 64.14 0 bottom
C276  1UF  [C0603]  196.85 63.12 270 bottom
C277  1UF  [C0603]  194.69 63.12 270 bottom
C278  0.1UF  [C0402]  191.64 63.25 270 bottom
C279  0.1UF  [C0402]  188.59 63.37 270 bottom
C280  1UF  [C0603]  186.94 63.5 270 bottom
C281  0.1UF  [C0402]  165.23 64.14 180 bottom
C282  0.1UF  [C0402]  161.04 64.14 0 bottom
C283  0.1UF  [C0402]  117.86 61.09 180 bottom
C284  100UF  [C1206H71]  93.6 62.48 180 bottom
C285  0.1UF  [C0402]  86.74 62.99 180 bottom
C286  0.1UF  [C0402]  78.61 61.54 90 bottom
C287  4.7UF  [C0402]  67.82 62.87 180 bottom
C288  0.1UF  [C0402]  64.77 64.77 270 bottom
C289  100UF  [C1210]  39.88 64.64 0 bottom
C290  100UF  [C1206H71]  39.75 60.58 0 bottom
C291  330UF  [C7343H162]  132.46 55.37 90 bottom
C292  0.1UF  [C0402]  86.74 58.04 180 bottom
C293  0.1UF  [C0402]  83.95 58.04 180 bottom
C294  0.1UF  [C0402]  75.06 58.04 0 bottom
C295  4.7UF  [C0402]  71.63 58.04 90 bottom
C296  4.7UF  [C0402]  69.85 58.04 90 bottom
C297  4.7UF  [C0402]  67.82 58.8 180 bottom
C298  4.7UF  [C0402]  67.82 54.99 0 bottom
C299  4.7UF  [C0402]  64.77 58.04 90 bottom
C300  4.7UF  [C0402]  62.74 58.04 90 bottom
C301  100UF  [C1206H71]  39.75 56.52 0 bottom
C302  0.1UF  [C0402]  118.11 49.66 180 bottom
C303  0.1UF  [C0402]  86.74 52.07 180 bottom
C304  0.1UF  [C0402]  77.22 52.96 0 bottom
C305  4.7UF  [C0402]  67.56 51.94 180 bottom
C306  4.7UF  [C0402]  67.56 50.17 180 bottom
C307  100UF  [C1210]  39.88 52.2 0 bottom
C308  0.1UF  [C0402]  98.68 45.85 180 bottom
C309  100UF  [C1206H71]  93.22 47.24 180 bottom
C310  4.7UF  [C0402]  80.64 45.47 90 bottom
C311  4.7UF  [C0402]  78.49 45.47 90 bottom
C312  4.7UF  [C0402]  74.55 45.47 90 bottom
C313  220UF  [CPLSML327W327H413]  167.26 144.53 180 top
C314  4.7UF  [C0402]  72.52 45.47 90 bottom
C315  4.7UF  [C0402]  68.2 45.21 0 bottom
C316  4.7UF  [C0402]  65.66 44.83 90 bottom
C317  100UF  [C1206H71]  39.75 48.01 0 bottom
C318  10UF  [C0805]  129.29 44.2 180 bottom
C319  0.1UF  [C0402]  118.11 42.67 180 bottom
C320  4.7UF  [C0402]  82.68 41.91 90 bottom
C321  4.7UF  [C0402]  78.61 41.91 90 bottom
C322  4.7UF  [C0402]  74.68 41.91 90 bottom
C323  4.7UF  [C0402]  67.69 41.53 90 bottom
C324  4.7UF  [C0402]  65.79 41.53 90 bottom
C325  4.7UF  [C0402]  63.88 41.53 90 bottom
C326  0.1UF  [C0402]  146.69 38.48 90 bottom
C327  0.1UF  [C0402]  129.92 39.37 180 bottom
C328  0.1UF  [C0402]  129.92 38.1 180 bottom
C329  0.1UF  [C0402]  129.92 36.58 180 bottom
C330  0.1UF  [C0402]  129.92 35.31 180 bottom
C331  10UF  [C0805]  118.11 38.86 180 bottom
C332  4.7UF  [C0402]  75.56 37.34 90 bottom
C333  4.7UF  [C0402]  73.66 37.34 90 bottom
C334  4.7UF  [C0402]  55.63 37.08 90 bottom
C335  0.1UF  [C0402]  137.8 33.4 180 bottom
C336  0.1UF  [C0402]  87 21.08 180 top
C337  1UF  [C0603]  20.07 30.35 180 bottom
C338  1UF  [C0603]  19.81 32.51 180 bottom
C339  0.1UF  [C0402]  181.36 24.26 180 bottom
C340  0.1UF  [C0402]  93.22 16.64 0 bottom
C341  1UF  [C0603]  19.68 26.67 180 bottom
C342  0.1UF  [C0402]  156.08 22.73 0 bottom
C343  0.1UF  [C0402]  153.29 22.73 180 bottom
C344  0.1UF  [C0402]  125.02 22.58 90 bottom
C345  0.1UF  [C0402]  122.43 23.37 0 bottom
C346  0.1UF  [C0402]  114.05 22.73 180 bottom
C347  10UF  [C0805]  114.05 16.26 0 bottom
C348  0.1UF  [C0402]  28.57 17.78 90 bottom
CN1  1000PF  [C-NET8P-0805]  100.71 103.25 270 bottom
CN2  1000PF  [C-NET8P-0805]  122.43 19.81 180 bottom
CN3  1000PF  [C-NET8P-0805]  66.42 115.95 0 bottom
CN4  1000PF  [C-NET8P-0805]  72.39 115.95 0 bottom
CN5  1000PF  [C-NET8P-0805]  74.3 107.44 0 bottom
CN6  1000PF  [C-NET8P-0805]  118.11 57.91 270 bottom
CN7  1000PF  [C-NET8P-0805]  100.97 111.63 270 bottom
CN8  1000PF  [C-NET8P-0805]  114.12 19.86 180 bottom
CN9  1000PF  [C-NET8P-0805]  101.85 107.57 270 bottom
CN10  1000PF  [C-NET8P-0805]  119.25 17.78 180 bottom
CN11  1000PF  [C-NET8P-0805]  126.49 60.33 270 bottom
CN12  1000PF  [C-NET8P-0805]  60.33 115.95 0 bottom
CN13  1000PF  [C-NET8P-0805]  126.49 55.25 270 bottom
CN14  1000PF  [C-NET8P-0805]  126.49 48.89 270 bottom
CN15  1000PF  [C-NET8P-0805]  92.84 107.44 0 bottom
CN16  1000PF  [C-NET8P-0805]  118.11 47.12 270 bottom
CN17  1000PF  [C-NET8P-0805]  101.73 114.81 0 bottom
CN18  1000PF  [C-NET8P-0805]  118.11 52.2 270 bottom
CR1  MMSZ4678T1G  [SOD123]  172.34 123.7 90 top
CR2  PGB1010603  [D0603]  196.09 100.33 180 top
CR4  PGB1010603  [D0603]  205.99 87.25 270 bottom
CR5  PGB1010603  [D0603]  203.96 87.25 270 bottom
D1  SMBJ13A-TR  [DO214AA1]  187.58 131.57 270 top
D2  MBRS540T3G  [SMC]  181.61 130.56 270 top
D3  DL4148  [DL35]  165.23 129.29 180 top
DS1  AA2214CGSK (GREEN)  [LEDSML90W55H55]  162.18 14.48 180 top
DS2  AA2214CGSK (GREEN)  [LEDSML90W55H55]  162.18 16.13 180 top
DS3  AA2214CGSK (GREEN)  [LEDSML90W55H55]  162.18 17.78 180 top
DS4  AA2214CGSK (GREEN)  [LEDSML90W55H55]  162.18 19.43 180 top
DS5  AA2214CGSK (GREEN)  [LEDSML90W55H55]  162.18 21.08 180 top
DS6  AA2214CGSK (GREEN)  [LEDSML90W55H55]  162.18 22.73 180 top
DS7  AA2214CGSK (GREEN)  [LEDSML90W55H55]  200.66 95.12 0 top
DS8  AA2214CGSK (GREEN)  [LEDSML90W55H55]  84.71 25.15 0 top
DS13  AA2214CGSK (GREEN)  [LEDSML90W55H55]  187.83 162.43 180 top
DS14  AA2214SURSK (RED)  [LEDSML90W55H55]  17.27 137.54 270 top
DS15  AA2214CGSK (GREEN)  [LEDSML90W55H55]  134.49 98.42 0 top
DS16  AA2214CGSK (GREEN)  [LEDSML90W55H55]  150.37 99.95 180 top
DS17  AA2214SURSK (RED)  [LEDSML90W55H55]  150.37 102.36 0 top
DS18  AA2214SURSK (RED)  [LEDSML90W55H55]  202.31 146.3 270 top
DS32  AA2214CGSK (GREEN)  [LEDSML90W55H55]  190.25 44.7 270 top
DS39  AA2214CGSK (GREEN)  [LEDSML90W55H55]  36.2 18.67 0 top
DS40  AA2214CGSK (GREEN)  [LEDSML90W55H55]  36.2 22.1 0 top
E1  600OHM  [L1206-3]  203.71 100.84 0 top
E2  600OHM  [L1206-3]  209.04 100.84 0 top
E3  600OHM  [L0805]  102.11 45.85 180 bottom
F1  8A  [F1206H46]  192.02 135.25 180 top
F2  0.05A  [F1210_A]  20.57 36.32 180 bottom
F3  0.50A  [F1206H30]  200.53 90.81 180 top
GP1  -  [JPSLD02]  7.77 19.43 0 top
J3  132255-11  [CNAMPHENOL132255-11]  212.6 45.47 0 top
J4  132255-11  [CNAMPHENOL132255-11]  212.6 30.1 0 top
J5  132255-11  [CNAMPHENOL132255-11]  212.6 75.95 0 top
J6  132255-11  [CNAMPHENOL132255-11]  212.6 60.58 0 top
L1  1.8UH  [LSML250W258H122]  38.61 166.62 180 top
L2  3.3UH  [LSML250W258H122]  38.61 153.16 180 top
L3  4.7UH  [LSMSQ157H122]  64.01 163.19 90 top
L4  4.7UH  [LSMSQ157H122]  64.01 156.21 270 top
L5  1.2UH  [LSML208W216H122]  108.59 166.24 180 top
L6  1.2UH  [LSML208W216H122]  108.59 153.8 180 top
L7  4.7UH  [LSMSQ157H122]  135.13 163.19 90 top
L8  4.7UH  [LSMSQ157H122]  135.13 156.21 270 top
L9  1.2UH  [LSML208W216H122]  157.23 83.95 90 top
L10  1.2UH  [LSML208W216H122]  169.42 83.95 90 top
L11  4.7UH  [LSMSQ157H122]  159.64 56.13 180 top
L12  4.7UH  [LSMSQ157H122]  166.62 56.13 0 top
NOREF  -  []  215.9 9.02 90 top
NOREF#2  -  []  0 0 90 top
NOREF#3  -  []  376.94 182.75 0 top
NOREF#4  -  []  74.8 65.15 0 top
NOREF#5  -  []  0 9.02 0 top
NOREF#6  -  [unnamed#2]  5.08 169.04 0 top
NOREF#7  -  []  -227.46 -219.46 0 top
NOREF#8  -  [unnamed#3]  110.74 17.65 90 top
NOREF#9  -  [unnamed#2]  13.97 15.37 0 top
NOREF#10  -  []  0 9.02 0 top
NOREF#11  -  [unnamed#2]  204.47 15.37 0 top
NOREF#12  -  []  403.35 165.48 0 top
NOREF#13  -  [unnamed#2]  210.82 169.04 0 top
NOREF#14  -  []  209.3 27.18 0 top
NOREF#15  -  [unnamed#3]  103.76 99.82 180 top
NOREF#16  -  []  214.88 24.64 90 top
NOREF#17  -  [unnamed#2]  5.08 158.88 0 top
NOREF#18  -  [unnamed#2]  5.08 94.11 0 top
NOREF#19  -  []  -131.83 185.67 0 top
NOREF#20  -  []  0 9.02 90 top
NOREF#21  -  [unnamed#2]  122.17 99.06 0 top
NOREF#22  -  []  105.16 190.25 0 top
NOREF#23  -  []  -228.47 -218.82 0 top
NOREF#24  -  [unnamed#2]  5.08 14.1 0 top
NOREF#25  -  []  0 9.02 90 top
NOREF#26  -  []  -227.84 -219.84 0 top
NOREF#27  -  []  358.14 9.02 0 top
NOREF#28  -  [unnamed#2]  210.82 14.1 0 top
NOREF#29  -  [unnamed#2]  5.08 158.88 180 bottom
NOREF#30  -  []  25.65 84.45 180 bottom
NOREF#31  -  [unnamed#2]  204.47 15.37 180 bottom
NOREF#32  -  [unnamed#2]  13.97 15.37 180 bottom
P1  ASP-134486-01  [CNSAMTECASP-134486-01]  10.16 50.93 270 top
P2  MOLEX22-23-2031  [CNMOLEX22-23-2031]  200.53 157.99 90 top
P3  87832-1420-TB32  [CNMOLEX87832-1420]  146.18 137.03 0 top
P4  22-11-2032  [CNMOLEX22-23-2031]  163.7 124.08 0 top
P5  AS0A626-U2SN-7F  [CNFOXAS0A626-U2SN-7F]  118.24 55.25 270 top
P6  AS0A626-U2SN-7F  [CNFOXAS0A626-U2SN-7F]  65.41 107.44 0 top
P7  39-30-1060  [CNHDRRA2X3H451]  201.8 120.27 270 top
P8  292304-1  [CNTYCO292304]  203.96 92.84 270 top
P9  CA-D20-24C-44  [CNBERG2X10H346LD36]  57.53 16.26 0 top
P10  TSM-107-01-T-DV  [CNHDR2X7H380]  200.66 26.8 90 top
P11  MOLEX22-23-2031  [CNMOLEX22-23-2031]  189.99 14.73 90 top
Q1  BSC072N03LD G  [PG-TDSON-8_A]  40.01 159.89 90 top
Q2  BSC072N03LD G  [PG-TDSON-8_A]  111.12 159.89 90 top
Q3  PSMN0R9-25YLC,115  [SOT669]  177.04 157.86 270 top
Q4  PSMN013-30LL  [SOT873-1]  14.35 121.28 180 top
Q5  PSMN013-30LL  [SOT873-1]  16.13 101.73 0 top
Q6  SI2333DS-T1-E3  [SOT23]  195.2 94.62 0 top
Q7  BSC072N03LD G  [PG-TDSON-8_A]  163.32 80.14 0 top
Q8  NDS331N  [SOT23]  175.64 18.41 0 top
Q9  NDS331N  [SOT23]  181.74 18.41 0 top
Q10  NDS331N  [SOT23]  190.88 161.42 180 bottom
Q11  NDS332P  [SOT23]  198.5 145.41 0 bottom
Q12  NDS332P  [SOT23]  17.27 130.68 180 bottom
Q13  SI2336DS-T1-GE3  [SOT23]  163.58 120.02 180 bottom
Q14  NDS331N  [SOT23]  190.25 48.39 0 bottom
Q15  NDS331N  [SOT23]  32.38 20.32 0 bottom
Q16  NDS331N  [SOT23]  36.83 17.91 180 bottom
R1  0.001  [R1206]  27.3 168.91 180 top
R2  10K  [R0402]  51.94 165.61 270 top
R3  10K  [R0402]  53.34 165.61 270 top
R4  10K  [R0402]  54.48 165.61 270 top
R5  499K  [R0402]  123.06 165.48 270 top
R6  10K  [R0402]  124.46 165.61 270 top
R7  200K  [R0402]  125.73 165.86 90 top
R8  499K  [R0402]  127 165.86 270 top
R9  22.1K  [R0402]  45.59 161.29 0 top
R10  22.1K  [R0402]  45.59 158.75 0 top
R11  0.015  [R0603]  73.41 161.29 0 top
R12  0.015  [R0603]  73.41 157.23 0 top
R13  0.001  [R1206]  97.54 159.89 180 top
R14  22.1K  [R0402]  116.71 161.29 0 top
R15  22.1K  [R0402]  116.71 158.75 0 top
R16  0.015  [R0603]  144.53 159.26 0 top
R17  51.1K  [R0805]  190.25 160.27 180 top
R18  6.65K  [R0805]  192.28 157.1 270 top
R19  0.001  [R1206]  27.3 151.89 180 top
R20  10K  [R0402]  51.05 153.03 90 top
R21  10K  [R0402]  56.64 154.18 90 top
R22  0  [R0402]  110.11 149.73 0 top
R23  8.87K  [R0402]  113.03 149.73 0 top
R24  10.2K  [R0402]  115.19 151.38 0 top
R25  10K  [R0402]  122.17 153.03 90 top
R26  10K  [R0402]  126.87 154.18 90 top
R27  10  [R0603]  183.77 152.02 180 top
R28  4.7K  [R0402]  197.23 152.65 90 top
R29  51.1K  [R0805]  202.06 151.51 0 top
R30  0  [R0402]  42.04 148.21 0 top
R31  0  [R0402]  42.04 146.43 0 top
R32  31.6K  [R0603]  45.47 146.43 0 top
R33  10.2K  [R0402]  48.9 146.43 0 top
R34  10K  [R0402]  53.98 147.19 180 top
R35  15K  [R0402]  57.28 147.19 180 top
R36  0  [R0402]  60.58 147.19 180 top
R37  10K  [R0402]  57.66 169.42 180 top
R38  4.99K  [R0402]  61.21 169.42 180 top
R39  0  [R0402]  64.64 170.81 180 top
R40  0  [R0402]  64.64 169.04 180 top
R41  0  [R0402]  110.11 148.08 0 top
R42  100K  [R0402]  125.48 149.73 270 top
R43  200K  [R0402]  168.91 68.2 0 bottom
R44  22.1K  [R0402]  162.18 74.55 270 top
R45  10K  [R0402]  128.91 147.07 180 top
R46  38.3K  [R0402]  160.15 67.82 180 bottom
R47  3.3K  [R0402]  131.95 147.07 180 top
R48  0  [R0402]  135 148.84 180 top
R49  0  [R0402]  135 147.07 180 top
R50  0.001  [R2512H31]  179.83 150.88 90 top
R51  51.1K  [R0805]  202.06 149.22 180 top
R52  1K  [R0402]  202.31 143 270 top
R53  147K  [R0402]  29.08 141.48 90 top
R54  0  [R0402]  60.58 145.41 180 top
R55  147K  [R0402]  66.93 141.48 90 top
R56  147K  [R0402]  96.52 141.48 90 top
R57  147K  [R0402]  97.79 141.48 90 top
R58  51.1K  [R0805]  184.28 144.27 180 top
R59  47K  [R0805]  187.32 142.62 270 top
R60  4.02K  [R1206]  189.74 143.38 90 top
R61  300  [R0402]  17.27 134.24 270 top
R62  4.64K  [R0402]  120.65 131.19 90 top
R63  10K  [R0402]  122.3 131.19 270 top
R64  200  [R0402]  129.54 131.19 270 top
R65  4.64K  [R0402]  120.65 128.52 270 top
R66  10K  [R0402]  122.3 128.52 270 top
R67  33  [R0402]  127.25 130.56 180 top
R68  33  [R0402]  127.25 129.16 180 top
R69  200  [R0402]  129.54 128.52 90 top
R70  100  [R0402]  110.11 121.28 270 top
R71  200  [R0402]  111.89 122.68 270 top
R72  200  [R0402]  124.84 121.41 270 top
R73  0  [R0402]  127.51 123.19 0 top
R74  200  [R0402]  133.48 124.84 270 top
R75  200  [R0402]  135.51 124.84 270 top
R76  0  [R0402]  139.7 123.32 180 top
R77  200  [R0402]  111.89 119.89 90 top
R78  200  [R0402]  124.84 118.62 90 top
R79  200  [R0402]  151.38 118.24 0 top
R80  33  [R0402]  152.02 115.95 270 top
R81  33  [R0402]  153.54 115.95 270 top
R82  200  [R0402]  154.05 118.24 180 top
R83  200  [R0402]  110.74 114.17 0 top
R84  33  [R0402]  111.38 111.89 270 top
R85  33  [R0402]  112.9 111.89 270 top
R86  200  [R0402]  113.41 114.17 180 top
R87  200  [R0402]  117.35 114.17 0 top
R88  33  [R0402]  117.98 111.89 270 top
R89  33  [R0402]  119.51 111.89 270 top
R90  200  [R0402]  120.02 114.17 180 top
R91  0  [R0402]  126.75 115.06 0 top
R92  1MEG  [R0402]  133.99 113.28 180 top
R93  1K  [R0402]  138.56 114.94 180 top
R94  200  [R0402]  141.73 115.57 0 top
R95  33  [R0402]  142.37 113.28 270 top
R96  33  [R0402]  143.89 113.28 270 top
R97  200  [R0402]  144.4 115.57 180 top
R98  10K  [R0402]  151.38 111.12 0 top
R99  10K  [R0402]  154.18 111.12 0 top
R100  10K  [R0402]  110.74 107.06 0 top
R101  10K  [R0402]  113.54 107.06 0 top
R102  10K  [R0402]  117.35 107.06 0 top
R103  10K  [R0402]  120.14 107.06 0 top
R104  2.40K  [R0402]  141.73 108.46 180 top
R105  10K  [R0402]  141.73 106.81 0 top
R106  2.40K  [R0402]  144.53 108.46 0 top
R107  10K  [R0402]  144.53 106.81 0 top
R108  2.40K  [R0402]  151.38 109.47 180 top
R109  2.40K  [R0402]  154.18 109.47 0 top
R110  147K  [R0402]  162.18 107.95 90 top
R111  22.1K  [R0402]  199.64 107.95 0 top
R112  31.6K  [R0402]  202.56 107.95 0 top
R113  0  [R1206]  11.94 101.73 270 top
R114  2.40K  [R0402]  110.74 105.41 180 top
R115  2.40K  [R0402]  113.54 105.41 0 top
R116  2.40K  [R0402]  117.35 105.41 180 top
R117  2.40K  [R0402]  120.14 105.41 0 top
R118  300  [R0402]  147.57 101.22 90 top
R119  300  [R0402]  150.5 104.39 180 top
R120  0  [R0402]  182.75 101.85 90 top
R121  100K  [R0402]  183.52 104.65 180 top
R122  100K  [R0402]  184.4 101.85 270 top
R123  10K  [R0402]  159.13 35.56 90 top
R124  10K  [R0402]  11.43 97.66 180 top
R125  10  [R0402]  18.03 97.66 270 top
R126  300  [R0402]  137.8 98.42 0 top
R127  0.001  [R1206]  162.81 95.25 90 top
R128  1K  [R0402]  199.52 100.33 0 top
R129  10K  [R0402]  178.56 95.25 90 top
R130  18K  [R0402]  180.21 95.25 270 top
R131  0  [R1206]  195.2 91.06 180 top
R132  300  [R0402]  200.66 93.09 180 top
R133  4.7K  [R0402]  173.86 90.17 0 top
R134  0  [R0402]  192.79 88.9 180 top
R135  0  [R0402]  192.79 87.25 180 top
R136  33  [R0402]  198.75 88.14 90 top
R137  330  [R0603]  184.53 82.68 180 top
R138  330  [R0603]  188.09 82.68 180 top
R139  1MEG  [R0603]  204.47 84.2 180 top
R140  100K  [R0402]  185.93 79.12 270 top
R141  100K  [R0402]  189.74 79.12 270 top
R142  0  [R0402]  207.14 75.31 270 top
R143  22.1K  [R0402]  164.72 74.55 270 top
R144  4.7K  [R0402]  207.77 73.03 180 top
R145  4.7K  [R0402]  207.77 70.74 0 top
R146  10K  [R0402]  156.46 69.09 0 top
R147  499K  [R0402]  168.91 68.2 180 top
R148  10K  [R0402]  169.04 66.8 180 top
R149  10K  [R0402]  169.04 65.53 180 top
R150  10K  [R0402]  157.61 64.39 0 top
R151  100  [R0402]  207.9 60.58 0 top
R152  0  [R0402]  198.63 57.53 0 top
R153  0  [R0402]  201.17 57.53 0 top
R154  0  [R0402]  183.9 50.04 270 top
R155  0  [R0402]  187.58 50.04 270 top
R156  0  [R0402]  189.23 50.04 90 top
R157  0.015  [R0603]  160.78 46.74 270 top
R158  0.015  [R0603]  164.72 46.74 270 top
R159  4.7K  [R0402]  172.47 46.48 90 top
R160  4.7K  [R0402]  174.12 46.48 90 top
R161  0  [R0402]  193.04 42.16 180 top
R162  0  [R0402]  193.04 40.77 180 top
R163  4.7K  [R0402]  204.72 41.02 270 top
R164  4.7K  [R0402]  206.12 41.02 90 top
R165  300  [R0402]  190.25 41.66 270 top
R166  0  [R0402]  193.04 38.73 180 top
R167  0  [R0402]  193.04 37.21 180 top
R168  1K  [R0402]  204.85 37.72 90 top
R169  1K  [R0402]  207.65 37.72 270 top
R170  10K  [R0402]  162.43 35.56 90 top
R171  4.7K  [R0402]  172.09 30.73 180 top
R172  4.7K  [R0402]  175.01 29.97 180 top
R173  4.7K  [R0402]  187.96 30.1 0 top
R174  100K  [R0402]  194.31 31.75 90 top
R175  0  [R0402]  207.77 30.73 90 top
R176  300  [R0402]  88.01 25.15 0 top
R177  10K  [R0402]  155.32 28.32 0 top
R178  4.7K  [R0402]  172.09 29.08 180 top
R179  4.7K  [R0402]  172.09 27.43 180 top
R180  4.7K  [R0402]  172.09 25.78 180 top
R181  4.7K  [R0402]  175.01 28.32 180 top
R182  4.7K  [R0402]  175.13 26.67 180 top
R183  4.7K  [R0402]  187.96 28.45 0 top
R184  4.7K  [R0402]  187.96 26.67 0 top
R185  4.7K  [R0402]  187.96 25.27 0 top
R186  4.7K  [R0402]  190.88 29.21 0 top
R187  4.7K  [R0402]  190.88 27.56 0 top
R188  4.7K  [R0402]  190.88 25.91 0 top
R189  4.7K  [R0402]  190.88 24.26 180 top
R190  100  [R0402]  100.08 26.54 180 bottom
R191  4.7K  [R0402]  103.63 29.34 90 bottom
R192  100  [R0402]  103.63 21.08 180 top
R193  4.7K  [R0402]  106.55 21.08 0 top
R194  300  [R0402]  158.88 22.73 180 top
R195  300  [R0402]  158.88 21.08 180 top
R196  300  [R0402]  158.88 19.43 180 top
R197  4.7K  [R0402]  176.28 21.46 0 top
R198  4.7K  [R0402]  182.37 21.59 0 top
R199  1K  [R0402]  184.53 162.43 180 top
R200  4.7K  [R0402]  187.96 23.62 180 top
R201  300  [R0402]  158.88 17.78 180 top
R202  300  [R0402]  158.88 16.13 180 top
R203  300  [R0402]  158.88 14.48 180 top
R204  4.7K  [R0402]  177.16 14.1 0 top
R205  4.7K  [R0402]  183.26 14.1 0 top
R206  1K  [R0603]  190.12 157.23 90 top
R207  10.2K  [R0402]  46.61 167.26 0 bottom
R208  12.7K  [R0402]  43.56 167.26 0 bottom
R209  0  [R0402]  41.15 169.55 270 bottom
R210  0  [R0402]  40.51 167.26 0 bottom
R211  10  [R0603]  14.48 125.86 180 top
R212  10K  [R0402]  193.68 161.8 90 bottom
R213  200K  [R0402]  123.06 165.48 90 bottom
R214  0  [R0402]  194.44 157.1 90 bottom
R215  2K  [R0402]  190.88 158.24 180 bottom
R216  38.3K  [R0402]  123.44 156.72 270 bottom
R217  38.3K  [R0402]  52.32 156.72 270 bottom
R218  4.7K  [R0402]  197.49 148.59 180 bottom
R219  4.7K  [R0402]  194.56 148.97 90 bottom
R220  2K  [R0402]  194.56 145.92 270 bottom
R221  147K  [R0402]  143.76 143.26 180 bottom
R222  10K  [R0402]  84.07 130.18 180 bottom
R223  4.7K  [R0402]  20.19 130.18 270 bottom
R224  10K  [R0402]  169.55 121.54 0 bottom
R225  200  [R0402]  151.38 120.78 270 bottom
R226  200  [R0402]  140.08 121.03 270 bottom
R227  0  [R0402]  137.92 121.16 270 bottom
R228  0  [R0402]  135.25 124.08 270 bottom
R229  0  [R0402]  133.1 124.08 270 bottom
R230  0  [R0402]  130.68 124.08 270 bottom
R231  2  [R1206]  186.31 154.43 180 top
R232  10K  [R0402]  91.69 124.84 180 bottom
R233  3.48K  [R0603]  169.93 118.11 180 bottom
R234  10K  [R0402]  169.55 119.89 180 bottom
R235  1K  [R0402]  166.5 119.51 270 bottom
R236  100  [R0402]  153.29 119.25 90 bottom
R237  200  [R0402]  151.38 117.86 90 bottom
R238  200  [R0402]  140.08 118.49 90 bottom
R239  0  [R0402]  127.51 120.52 0 bottom
R240  4.7K  [R0402]  95.63 111.63 270 bottom
R241  4.7K  [R0402]  42.42 115.06 270 bottom
R242  4.7K  [R0402]  57.79 109.22 90 bottom
R243  4.7K  [R0402]  57.79 105.54 270 bottom
R244  22  [R0603]  183.13 147.32 270 top
R245  10  [R0603]  183.77 149.99 180 top
R246  4.7K  [R0402]  95.38 103.25 270 bottom
R247  76.8K  [R0402]  192.02 93.22 0 bottom
R248  80.6  [R0603]  79.63 83.19 270 bottom
R249  80.6  [R0603]  77.72 83.19 90 bottom
R250  80.6  [R0603]  73.03 83.19 270 bottom
R251  80.6  [R0603]  70.99 83.19 90 bottom
R252  80.6  [R0603]  67.06 83.31 270 bottom
R253  80.6  [R0603]  65.15 83.31 90 bottom
R254  80.6  [R0603]  61.09 83.31 270 bottom
R255  80.6  [R0603]  59.18 83.31 90 bottom
R256  4.7K  [R0402]  16.13 82.55 0 bottom
R257  100K  [R0603]  194.69 145.67 180 top
R258  23.2K  [R0603]  194.69 143.38 0 top
R259  10K  [R0402]  16.13 80.52 0 bottom
R260  33  [R0402]  197.87 79.25 270 bottom
R261  33  [R0402]  194.69 79.12 90 bottom
R262  33  [R0402]  193.04 78.99 90 bottom
R263  33  [R0402]  191.52 78.99 90 bottom
R264  0  [R0402]  156.9 72.77 270 bottom
R265  2.49K  [R0402]  156.84 69.98 270 bottom
R266  0  [R0402]  155.24 72.8 270 bottom
R267  10K  [R0402]  154.53 69.29 180 bottom
R268  4.7K  [R0402]  125.73 78.11 180 bottom
R269  100  [R0402]  60.71 77.72 270 bottom
R270  100  [R0402]  57.4 77.72 270 bottom
R271  100  [R0402]  55.63 77.72 90 bottom
R272  1K  [R0402]  86.87 73.91 0 bottom
R273  0.08  [R1206]  18.16 118.36 90 top
R274  1K  [R0402]  86.87 72.26 180 bottom
R275  100K  [R0402]  203.71 68.2 180 bottom
R276  100K  [R0402]  203.71 67.18 180 bottom
R277  100K  [R0402]  203.71 66.17 0 bottom
R278  100K  [R0402]  203.71 65.15 0 bottom
R279  10.2K  [R0402]  170.56 61.59 90 bottom
R280  10.2K  [R0402]  154.56 61.85 90 bottom
R281  4.7K  [R0402]  121.41 62.87 180 bottom
R282  4.7K  [R0402]  116.33 62.87 180 bottom
R283  100  [R0402]  44.07 59.82 180 bottom
R284  33  [R0402]  189.74 57.53 90 bottom
R285  33  [R0402]  188.34 57.53 90 bottom
R286  0  [R0402]  172.21 55.5 90 bottom
R287  13K  [R0402]  170.56 58.55 90 bottom
R288  0  [R0402]  170.56 55.5 90 bottom
R289  0  [R0402]  156.34 55.5 90 bottom
R290  31.6K  [R0402]  154.56 58.55 90 bottom
R291  0  [R0402]  154.56 55.5 90 bottom
R292  80.6  [R0603]  92.2 58.8 0 bottom
R293  80.6  [R0603]  92.2 56.9 180 bottom
R294  100  [R0402]  44.07 57.91 180 bottom
R295  100  [R0402]  44.07 56.01 180 bottom
R296  4.7K  [R0402]  181.23 50.67 270 bottom
R297  80.6  [R0603]  92.33 52.96 180 bottom
R298  80.6  [R0603]  92.33 51.05 0 bottom
R299  100K  [R0402]  186.44 46.36 270 bottom
R300  100K  [R0402]  184.66 46.36 270 bottom
R301  100  [R0201]  79.25 54.66 0 bottom
R302  100K  [R0402]  182.88 46.36 270 bottom
R303  100  [R0402]  86.36 46.1 180 bottom
R304  330  [R0402]  67.69 47.5 270 bottom
R305  4.7K  [R0402]  64.77 47.57 270 bottom
R306  1K  [R0402]  145.03 38.48 90 bottom
R307  1K  [R0402]  143.38 38.48 270 bottom
R308  1.21K  [R0402]  71.25 37.21 270 bottom
R309  1.21K  [R0402]  68.96 37.21 270 bottom
R310  4.7K  [R0402]  66.8 37.21 270 bottom
R311  4.7K  [R0402]  64.9 37.21 270 bottom
R312  100  [R0402]  61.21 37.21 90 bottom
R313  100  [R0402]  59.56 37.21 90 bottom
R314  100K  [R0402]  185.42 33.15 180 bottom
R315  100  [R0402]  92.84 21.72 90 top
R316  4.7K  [R0402]  122.43 25.4 180 bottom
R317  4.7K  [R0402]  116.59 26.04 270 bottom
R318  4.7K  [R0402]  114.17 24.51 180 bottom
R319  4.7K  [R0402]  92.84 24.38 90 top
R320  4.7K  [R0402]  89.53 13.84 0 bottom
R321  300  [R0402]  36.83 22.61 270 bottom
R322  10K  [R0402]  32.13 23.5 0 bottom
R323  4.7K  [R0402]  25.91 21.97 180 bottom
R324  40.2K  [R0402]  21.84 20.83 180 bottom
R325  10.5K  [R0402]  21.84 19.18 0 bottom
R326  0  [R0402]  180.21 14.1 180 bottom
R327  0  [R0402]  172.85 14.1 180 bottom
R328  1.21K  [R0402]  51.82 18.54 0 bottom
R329  1.21K  [R0402]  49.28 18.54 0 bottom
R330  1.21K  [R0402]  46.74 18.54 0 bottom
R331  100  [R0201]  78.23 57.53 0 bottom
R332  1.21K  [R0402]  44.2 18.54 0 bottom
R333  1.21K  [R0402]  41.66 18.54 0 bottom
R334  300  [R0402]  39.62 20.83 90 bottom
R335  4.7K  [R0402]  25.91 14.48 180 bottom
R336  40.2K  [R0402]  21.84 17.14 180 bottom
R337  36K  [R0402]  21.84 15.49 0 bottom
R338  0  [R0402]  180.21 12.45 180 bottom
